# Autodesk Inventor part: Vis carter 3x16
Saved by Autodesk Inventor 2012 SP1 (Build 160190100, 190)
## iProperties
Created: 2014-12
Part Number: Vis carter 3x16
Material: Default
Document SubType Name: Modeling
Designer: Bruno
Density: 1 g/cm^3
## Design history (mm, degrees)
node "Vis carter 3x161"
node "Vis carter 3x16"
node "Base1"
